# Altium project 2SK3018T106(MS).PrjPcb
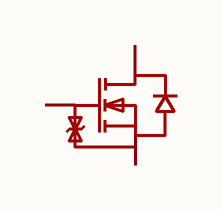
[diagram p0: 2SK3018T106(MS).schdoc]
1 sheet, 1 parts. Net scope: global (net labels, ports and power ports of the same name join across sheets).

## Sheet 2SK3018T106(MS).schdoc
size 127 x 101 mm

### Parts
Q?  2sk3018t106(ms)  [SOT-323-3_L2.1-W1.3-P1.30-LS2.3-BL]  (value not drawn)

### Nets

Not connected (* = marked no-connect by the designer): Q? 1(G) 2(S) 3(D)

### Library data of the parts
Q? = 2sk3018t106(ms): 数量:1个N沟道;漏源电压(Vdss):30V;连续漏极电流(Id):300mA;导通电阻(RDS(on)):4Ω@4.5V;耗散功率(Pd):200mW;阈值电压(Vgs(th)):1.6V;; Manufacturer: MSKSEMI(美森科); AddInBom: yes; ModelId: ecec1a5a289c42eb936c2652d367bf18; ModelTransform: 82.677,90.551,0,0,0,0,0,0,0; Number: 1个N沟道; Drain to Source Voltage: 30V; Current - Continuous Drain(Id): 300mA; Pd - Power Dissipation: 200mW; Gate Threshold Voltage (Vgs(th)): 1.6V; Input Capacitance(Ciss): 46pF; Reverse Transfer Capacitance (Crss@Vds): 20pF; Output Capacitance(Coss): 32pF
